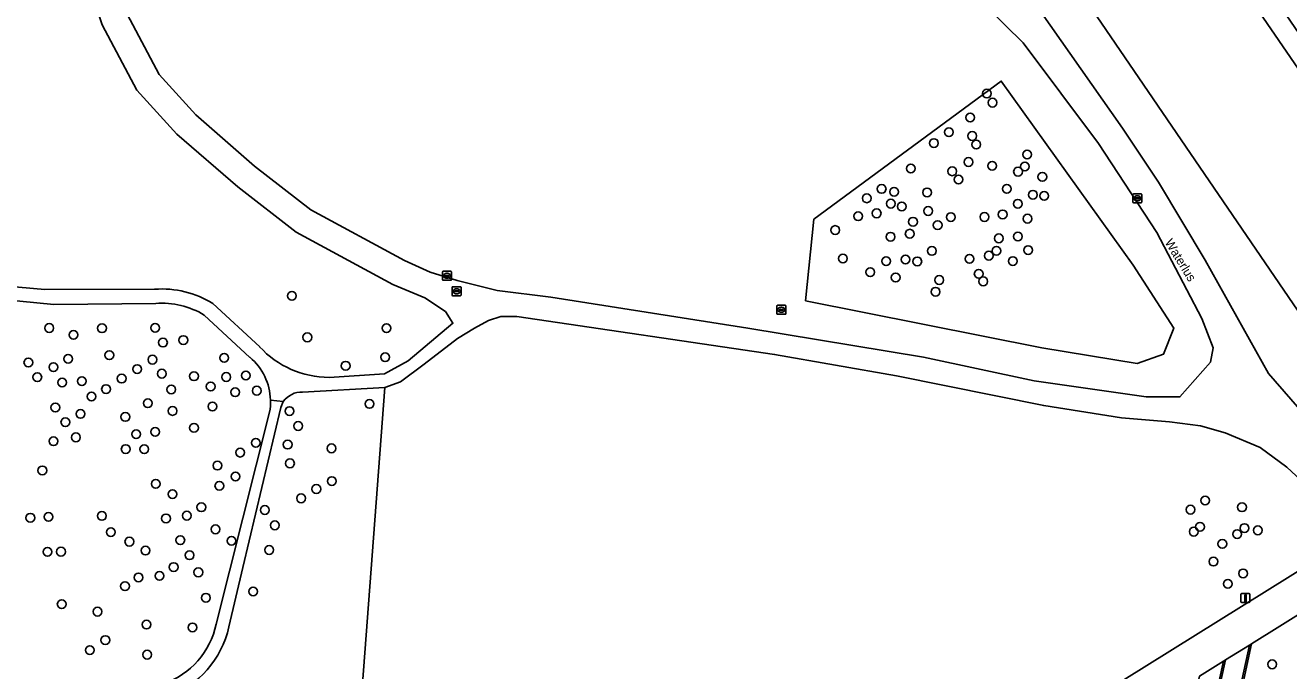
# Model space of a CAD drawing. Extents: x 155275 to 156265, y 382654 to 383635.
# Drawn here: x 155353.3 to 155494.7, y 383068.6 to 383140.8 of the extents above; entities that cross this region are included whole.
import ezdxf

# ---------------------------------------------------------------- set-up
doc = ezdxf.new("R2010")
doc.units = 0
for name, color, linetype in [('IMGEO_Boom', 7, 'Continuous'), ('IMGEO_Brandkraan', 7, 'Continuous'), ('IMGEO_Groenvoorziening', 7, 'Continuous'), ('IMGEO_Lichtmast', 7, 'Continuous'), ('IMGEO_Loofbos', 7, 'Continuous'), ('IMGEO_Openbare_ruimte_label', 7, 'Continuous'), ('IMGEO_Parkeervlak_halfverhard', 7, 'Continuous'), ('IMGEO_Parkeervlak_open', 7, 'Continuous'), ('IMGEO_Rijbaan_lokaal_halfverhard', 7, 'Continuous'), ('IMGEO_Rioolput', 7, 'Continuous'), ('IMGEO_Voetpad_halfverhard', 7, 'Continuous'), ('IMGEO_Voetpad_open', 7, 'Continuous')]:
    doc.layers.add(name, color=color, linetype=linetype)

msp = doc.modelspace()

# ---------------------------------------------------------------- linework, layer by layer
at = {"layer": 'IMGEO_Boom'}
for centre in [(155460.88, 383133.16), (155461.51, 383132.15), (155459.02, 383130.49), (155456.64, 383128.84), (155454.96, 383127.63), (155459.25, 383128.42), (155459.7, 383127.47), (155465.39, 383126.35), (155452.37, 383124.78), (155458.83, 383125.51), (155461.48, 383125.09), (155465.14, 383125.01), (155457.01, 383124.47), (155457.71, 383123.55), (155464.37, 383124.43), (155467.09, 383123.85), (155449.11, 383122.5), (155450.5, 383122.18), (155454.19, 383122.11), (155463.11, 383122.51), (155466.04, 383121.85), (155467.3, 383121.72), (155447.44, 383121.45), (155450.14, 383120.85), (155451.36, 383120.54), (155464.34, 383120.84), (155446.49, 383119.44), (155448.55, 383119.77), (155454.32, 383120.03), (155456.86, 383119.35), (155460.61, 383119.36), (155462.65, 383119.65), (155465.43, 383119.17), (155443.92, 383117.9), (155452.25, 383117.49), (155452.62, 383118.83), (155455.38, 383118.45), (155450.11, 383117.15), (155462.23, 383116.97), (155464.36, 383117.17), (155444.78, 383114.71), (155454.74, 383115.56), (155458.94, 383114.68), (155461.11, 383115.03), (155461.95, 383115.58), (155465.5, 383115.66), (155449.61, 383114.42), (155451.78, 383114.6), (155453.1, 383114.39), (155463.79, 383114.43), (155447.84, 383113.19), (155450.68, 383112.59), (155455.56, 383112.31), (155459.97, 383113), (155460.48, 383112.16), (155383.13, 383110.54), (155455.15, 383111), (155355.98, 383106.94), (155358.69, 383106.17), (155361.88, 383106.91), (155367.82, 383106.96), (155393.71, 383106.92), (155368.7, 383105.31), (155370.98, 383105.59), (155384.85, 383105.9), (155358.09, 383103.5), (155362.7, 383103.9), (155367.52, 383103.4), (155375.55, 383103.6), (155393.56, 383103.67), (155353.64, 383103.08), (155356.44, 383102.56), (155365.82, 383102.35), (155389.14, 383102.72), (155354.64, 383101.44), (155357.42, 383100.84), (155359.63, 383100.99), (155364.08, 383101.28), (155368.57, 383101.83), (155372.17, 383101.54), (155375.78, 383101.46), (155377.98, 383101.63), (155360.7, 383099.28), (155362.33, 383100.11), (155369.63, 383100.07), (155374.04, 383100.4), (155376.78, 383099.75), (155379.19, 383099.93), (155356.66, 383098.05), (155367, 383098.52), (155374.23, 383098.16), (155391.81, 383098.45), (155357.78, 383096.4), (155359.48, 383097.33), (155364.49, 383096.99), (155369.78, 383097.66), (155382.85, 383097.65), (155365.7, 383095.06), (155367.83, 383095.32), (155372.17, 383095.78), (155383.83, 383095.98), (155356.46, 383094.27), (155358.96, 383094.71), (155379.09, 383094.1), (155382.65, 383093.9), (155387.56, 383093.48), (155364.53, 383093.4), (155366.61, 383093.38), (155377.34, 383093), (155355.2, 383091.01), (155374.79, 383091.55), (155382.91, 383091.8), (155367.89, 383089.51), (155375.01, 383089.29), (155376.82, 383090.33), (155387.59, 383089.82), (155369.77, 383088.36), (155384.15, 383087.89), (155385.86, 383088.93), (155372.99, 383086.89), (155380.1, 383086.58), (155483.66, 383086.62), (155485.3, 383087.64), (155489.43, 383086.89), (155353.86, 383085.72), (155355.9, 383085.81), (155361.87, 383085.92), (155369.04, 383085.64), (155371.37, 383085.95), (155362.87, 383084.11), (155374.57, 383084.42), (155381.22, 383084.87), (155484.03, 383084.16), (155484.73, 383084.7), (155488.89, 383083.89), (155489.7, 383084.56), (155491.2, 383084.31), (155364.94, 383083.04), (155370.64, 383083.21), (155376.37, 383083.14), (155487.23, 383082.79), (155355.78, 383081.9), (155357.29, 383081.92), (155366.74, 383082.04), (155371.68, 383081.52), (155380.58, 383082.11), (155486.23, 383080.81), (155369.9, 383080.2), (155372.66, 383079.61), (155489.55, 383079.49), (155364.45, 383078.06), (155365.96, 383079.04), (155368.31, 383079.21), (155487.85, 383078.33), (155373.51, 383076.77), (155378.79, 383077.47), (155357.37, 383076.05), (155361.38, 383075.21), (155366.85, 383073.76), (155372, 383073.45), (155360.51, 383070.91), (155362.25, 383072.03), (155366.94, 383070.4), (155492.81, 383069.32)]:
    msp.add_circle(centre, 0.489, dxfattribs=at)
at = {"layer": 'IMGEO_Brandkraan'}
for p, q in [((155437.47, 383109.48), (155438.32, 383109.48)), ((155437.4, 383108.55), (155437.4, 383109.41)), ((155438.32, 383108.48), (155437.47, 383108.48)), ((155437.65, 383108.97), (155437.65, 383108.99)), ((155438.09, 383108.94), (155437.69, 383108.94)), ((155437.7, 383109.02), (155438.09, 383109.02)), ((155437.88, 383109.26), (155437.91, 383109.26)), ((155437.91, 383108.7), (155437.88, 383108.7)), ((155438.14, 383108.99), (155438.14, 383108.97)), ((155438.4, 383109.41), (155438.4, 383108.55))]:
    msp.add_line(p, q, dxfattribs=at)
for points in [[(155437.47, 383109.48), (155438.32, 383109.48)], [(155437.4, 383108.55), (155437.4, 383109.41)], [(155438.32, 383108.48), (155437.47, 383108.48)], [(155438.4, 383109.41), (155438.4, 383108.55)]]:
    msp.add_lwpolyline(points, dxfattribs=at)
for centre, radius, start, end in [((155437.47, 383109.4), 0.0765, 91.552, 178.448), ((155437.47, 383109.4), 0.0765, 91.552, 178.448), ((155438.32, 383109.4), 0.0765, 1.552, 88.448), ((155438.32, 383109.4), 0.0765, 1.552, 88.448), ((155437.47, 383108.55), 0.0765, 181.552, 268.448), ((155437.47, 383108.55), 0.0765, 181.552, 268.448), ((155437.69, 383108.98), 0.0403, 85.8775, 175.7526), ((155437.69, 383108.97), 0.0366, 178.938, 274.7102), ((155438.1, 383108.98), 0.0386, 1.7309, 96.639), ((155438.1, 383108.98), 0.043, 264.8664, 352.4533), ((155438.32, 383108.55), 0.0765, 271.552, 358.448), ((155438.32, 383108.55), 0.0765, 271.552, 358.448)]:
    msp.add_arc(centre, radius, start, end, dxfattribs=at)
for centre, major_axis, ratio, start_param, end_param in [((155437.88, 383108.98), (-0.387, 0.002), 0.722429, 4.712389, 7.853982), ((155437.91, 383108.98), (-0.39, 0.002), 0.717154, 1.570796, 4.712389)]:
    msp.add_ellipse(centre, major_axis=major_axis, ratio=ratio, start_param=start_param, end_param=end_param, dxfattribs=at)
at = {"layer": 'IMGEO_Groenvoorziening'}
for points in [[(155480.03, 383158.88), (155477.83, 383162.13), (155472.81, 383162.13), (155468.62, 383161.33), (155465.99, 383160.57), (155463.85, 383159.26), (155462.23, 383157.91), (155532.26, 383055.3), (155545.15, 383064.13), (155544.46, 383065.14), (155543.8, 383064.76), (155530.65, 383083.86), (155531.33, 383084.3), (155531.27, 383084.39), (155521.54, 383098.33)], [(155440.6, 383109.98), (155441.54, 383119.11), (155462.49, 383134.56), (155477.24, 383113.96), (155481.8, 383106.94), (155480.63, 383104.01), (155477.71, 383102.96), (155467.05, 383104.72)], [(155440.6, 383109.98), (155467.05, 383104.72), (155477.71, 383102.96), (155480.63, 383104.01), (155481.8, 383106.94), (155477.24, 383113.96), (155462.49, 383134.56), (155441.54, 383119.11)], [(155505.09, 383070.96), (155505.34, 383071.12), (155500.61, 383077.91), (155490.49, 383071.62), (155489.51, 383067.1), (155491.73, 383066.59), (155491.92, 383066.54), (155491.78, 383065.9), (155490.94, 383062.14)]]:
    msp.add_lwpolyline(points, close=True, dxfattribs=at)
for points in [[(155462.23, 383157.91), (155462.08, 383157.79), (155460.8, 383156.2), (155460.21, 383154.22), (155460.31, 383152.94), (155463.29, 383147.49), (155476.06, 383129.31), (155480.08, 383123.25), (155485.32, 383114.54), (155492.39, 383101.86), (155501.64, 383091.21), (155505.49, 383085.67), (155519.41, 383065.24), (155519.67, 383065.42), (155525.58, 383056.8)], [(155531.84, 383055.02), (155532.26, 383055.3), (155462.23, 383157.91)], [(155364.68, 383142.04), (155368.26, 383135.3), (155372.37, 383130.77), (155378.96, 383125.06), (155385.25, 383120.17), (155395.71, 383114.5), (155398.58, 383113.17), (155401.61, 383112.24), (155406.1, 383111.12), (155412.11, 383110.39), (155434.14, 383106.94), (155453.79, 383103.69), (155466.18, 383101.04), (155478.72, 383099.24), (155482.49, 383099.24), (155485.9, 383103.12), (155486.19, 383104.72), (155484.94, 383108), (155479.9, 383117.61), (155473.39, 383127.59), (155464.94, 383138.83), (155460.95, 383142.74)], [(155367.89, 383109.68), (155356.48, 383109.58), (155349.21, 383110.28)], [(155378.43, 383103.66), (155373.32, 383108.39)], [(155497.62, 383088.41), (155494.46, 383091.39), (155491.46, 383093.56), (155487.54, 383095.2), (155484.79, 383096.01), (155481.31, 383096.43), (155475.93, 383096.91), (155467.24, 383098.26), (155450.78, 383101.59), (155437.13, 383103.98), (155408.3, 383108.22), (155406.5, 383108.22), (155405.12, 383107.78), (155403.54, 383106.92), (155401.66, 383105.75), (155397.94, 383102.88), (155395.26, 383100.93), (155393.54, 383100.28), (155388.34, 383031.51), (155404.62, 383006.03), (155408.35, 383007.04), (155400.27, 383020.26), (155497.7, 383080.98)], [(155389.73, 383006.22), (155391.23, 383005.97), (155393.49, 383005.33), (155395.95, 383004.69), (155380.85, 383027.06), (155378.28, 383034.08), (155367.51, 383058.66), (155376.17, 383061.23), (155388.34, 383031.51), (155393.54, 383100.28)], [(155393.54, 383100.28), (155384.32, 383099.78)], [(155382.16, 383098.72), (155381.89, 383098.04), (155377.62, 383080.16), (155376.08, 383073.5)], [(155374.65, 383073.82), (155380.62, 383097.52)]]:
    msp.add_lwpolyline(points, dxfattribs=at)
for centre, radius, start, end in [((155368.57, 383100.49), 9.22, 58.989, 94.2431), ((155374.22, 383098.7), 6.51, 1.5857, 49.7196), ((155384.24, 383097.21), 2.57, 88.3524, 143.9444), ((155374.28, 383098.7), 6.46, 349.4798, 1.6068), ((155365.77, 383075.71), 9.09, 289.5801, 347.9592), ((155365.14, 383076.06), 11.24, 291.623, 346.8066)]:
    msp.add_arc(centre, radius, start, end, dxfattribs=at)
at = {"layer": 'IMGEO_Lichtmast'}
for p, q in [((155489.31, 383076.33), (155489.31, 383077.13)), ((155489.31, 383077.13), (155489.31, 383076.33)), ((155489.41, 383077.23), (155490.2, 383077.23)), ((155490.2, 383077.23), (155489.41, 383077.23)), ((155490.3, 383077.13), (155490.3, 383076.33)), ((155490.3, 383076.33), (155490.3, 383077.13)), ((155490.2, 383076.23), (155489.41, 383076.23)), ((155489.41, 383076.23), (155490.2, 383076.23))]:
    msp.add_line(p, q, dxfattribs=at)
msp.add_lwpolyline([(155489.73, 383077.1), (155489.88, 383077.1), (155489.88, 383076.35), (155489.73, 383076.35), (155489.73, 383077.1)], dxfattribs=at)
for centre, start, end in [((155489.41, 383077.13), 90, 180), ((155489.41, 383077.13), 90, 180), ((155490.2, 383077.13), 0, 90), ((155490.2, 383077.13), 360, 90), ((155489.41, 383076.33), 180, 270), ((155489.41, 383076.33), 180, 270), ((155490.2, 383076.33), 270, 0), ((155490.2, 383076.33), 270, 0)]:
    msp.add_arc(centre, 0.1, start, end, dxfattribs=at)
at = {"layer": 'IMGEO_Loofbos'}
for points in [[(155387.29, 383101.41), (155393.5, 383101.8), (155396.13, 383103.27), (155401.15, 383107.48), (155400.32, 383108.77), (155398, 383110.31), (155394.43, 383111.79), (155383.6, 383117.66), (155377.06, 383122.74), (155370.27, 383128.62), (155365.78, 383133.56), (155361.91, 383140.85), (155359.8, 383147.24), (155359.02, 383150.58), (155359.02, 383168.78), (155360.3, 383173.98), (155361.71, 383177.9), (155364.9, 383184), (155367.14, 383187.73), (155369.98, 383191.02), (155371.19, 383193.05), (155372.79, 383196.95), (155353.44, 383187.35)], [(155349.16, 383111.81), (155355.5, 383111.25), (155367.77, 383111.28)], [(155374.29, 383109.67), (155379.52, 383104.84)]]:
    msp.add_lwpolyline(points, dxfattribs=at)
for centre, radius, start, end in [((155368.57, 383100.5), 10.81, 58.0691, 94.2517), ((155387.29, 383111.96), 10.54, 222.4807, 269.9956)]:
    msp.add_arc(centre, radius, start, end, dxfattribs=at)
at = {"layer": 'IMGEO_Parkeervlak_halfverhard'}
for points in [[(155490.26, 383071.47), (155487.59, 383069.81), (155485.1, 383058.5), (155487.79, 383060.18)], [(155487.35, 383069.66), (155484.69, 383068), (155483.85, 383064.21), (155486.05, 383063.73)]]:
    msp.add_lwpolyline(points, close=True, dxfattribs=at)
at = {"layer": 'IMGEO_Parkeervlak_open'}
for points in [[(155489.51, 383067.1), (155490.49, 383071.62), (155490.38, 383071.54), (155490.26, 383071.47), (155487.79, 383060.18), (155487.91, 383060.26), (155488.03, 383060.33), (155489.36, 383066.44)], [(155487.59, 383069.81), (155487.47, 383069.74), (155487.35, 383069.66), (155486.05, 383063.73), (155485.72, 383062.26), (155484.86, 383058.35), (155484.98, 383058.43), (155485.1, 383058.5)]]:
    msp.add_lwpolyline(points, close=True, dxfattribs=at)
at = {"layer": 'IMGEO_Rijbaan_lokaal_halfverhard'}
for points in [[(155497.7, 383080.98), (155400.27, 383020.26), (155408.35, 383007.04), (155408.38, 383006.99), (155425.36, 383017.56)], [(155484.69, 383068), (155487.35, 383069.66), (155487.47, 383069.74), (155487.59, 383069.81), (155490.26, 383071.47), (155490.38, 383071.54), (155490.49, 383071.62), (155500.61, 383077.91)]]:
    msp.add_lwpolyline(points, dxfattribs=at)
at = {"layer": 'IMGEO_Rioolput'}
for p, q in [((155477.21, 383121.02), (155477.21, 383121.87)), ((155477.29, 383121.94), (155478.14, 383121.94)), ((155478.14, 383120.94), (155477.29, 383120.94)), ((155477.47, 383121.44), (155477.47, 383121.45)), ((155477.51, 383121.49), (155477.91, 383121.49)), ((155477.91, 383121.4), (155477.51, 383121.4)), ((155477.7, 383121.72), (155477.72, 383121.72)), ((155477.72, 383121.16), (155477.7, 383121.16)), ((155477.95, 383121.45), (155477.95, 383121.44)), ((155478.21, 383121.87), (155478.21, 383121.02)), ((155399.97, 383112.36), (155399.97, 383113.21)), ((155400.05, 383113.29), (155400.9, 383113.29)), ((155400.23, 383112.78), (155400.23, 383112.79)), ((155400.67, 383112.74), (155400.27, 383112.74)), ((155400.28, 383112.83), (155400.67, 383112.83)), ((155400.46, 383113.06), (155400.49, 383113.06)), ((155400.48, 383112.51), (155400.46, 383112.51)), ((155400.72, 383112.79), (155400.72, 383112.78)), ((155400.98, 383113.21), (155400.98, 383112.36)), ((155400.9, 383112.28), (155400.05, 383112.28)), ((155401.05, 383110.63), (155401.05, 383111.48)), ((155401.12, 383111.55), (155401.98, 383111.55)), ((155401.31, 383111.05), (155401.31, 383111.06)), ((155401.35, 383111.1), (155401.75, 383111.1)), ((155401.74, 383111.01), (155401.35, 383111.01)), ((155401.54, 383111.33), (155401.56, 383111.33)), ((155401.79, 383111.06), (155401.79, 383111.05)), ((155402.05, 383111.48), (155402.05, 383110.63)), ((155401.98, 383110.55), (155401.12, 383110.55)), ((155401.56, 383110.77), (155401.53, 383110.77))]:
    msp.add_line(p, q, dxfattribs=at)
for points in [[(155477.21, 383121.02), (155477.21, 383121.87)], [(155477.29, 383121.94), (155478.14, 383121.94)], [(155478.14, 383120.94), (155477.29, 383120.94)], [(155478.21, 383121.87), (155478.21, 383121.02)], [(155399.97, 383112.36), (155399.97, 383113.21)], [(155400.05, 383113.29), (155400.9, 383113.29)], [(155400.98, 383113.21), (155400.98, 383112.36)], [(155400.9, 383112.28), (155400.05, 383112.28)], [(155401.05, 383110.63), (155401.05, 383111.48)], [(155401.12, 383111.55), (155401.98, 383111.55)], [(155402.05, 383111.48), (155402.05, 383110.63)], [(155401.98, 383110.55), (155401.12, 383110.55)]]:
    msp.add_lwpolyline(points, dxfattribs=at)
for centre, radius, start, end in [((155477.29, 383121.87), 0.0765, 91.552, 178.448), ((155477.29, 383121.87), 0.0765, 91.552, 178.448), ((155477.29, 383121.02), 0.0765, 181.552, 268.448), ((155477.29, 383121.02), 0.0765, 181.552, 268.448), ((155477.51, 383121.45), 0.0403, 85.8775, 175.7526), ((155477.51, 383121.44), 0.0366, 178.938, 274.7102), ((155477.92, 383121.45), 0.0386, 1.7309, 96.639), ((155477.91, 383121.44), 0.043, 264.8664, 352.4533), ((155478.14, 383121.87), 0.0765, 1.552, 88.448), ((155478.14, 383121.87), 0.0765, 1.552, 88.448), ((155478.14, 383121.02), 0.0765, 271.552, 358.448), ((155478.14, 383121.02), 0.0765, 271.552, 358.448), ((155400.05, 383113.21), 0.0765, 91.552, 178.448), ((155400.05, 383113.21), 0.0765, 91.552, 178.448), ((155400.05, 383112.36), 0.0765, 181.552, 268.448), ((155400.05, 383112.36), 0.0765, 181.552, 268.448), ((155400.27, 383112.79), 0.0403, 85.8775, 175.7526), ((155400.27, 383112.78), 0.0366, 178.938, 274.7102), ((155400.68, 383112.79), 0.0386, 1.7309, 96.639), ((155400.67, 383112.78), 0.043, 264.8664, 352.4533), ((155400.9, 383113.21), 0.0765, 1.552, 88.448), ((155400.9, 383113.21), 0.0765, 1.552, 88.448), ((155400.9, 383112.36), 0.0765, 271.552, 358.448), ((155400.9, 383112.36), 0.0765, 271.552, 358.448), ((155401.12, 383111.48), 0.0765, 91.552, 178.448), ((155401.12, 383111.48), 0.0765, 91.552, 178.448), ((155401.35, 383111.06), 0.0403, 85.8775, 175.7526), ((155401.34, 383111.05), 0.0366, 178.938, 274.7102), ((155401.75, 383111.05), 0.043, 264.8664, 352.4533), ((155401.75, 383111.06), 0.0386, 1.7309, 96.639), ((155401.97, 383111.48), 0.0765, 1.552, 88.448), ((155401.97, 383111.48), 0.0765, 1.552, 88.448), ((155401.12, 383110.63), 0.0765, 181.552, 268.448), ((155401.12, 383110.63), 0.0765, 181.552, 268.448), ((155401.97, 383110.63), 0.0765, 271.552, 358.448), ((155401.97, 383110.63), 0.0765, 271.552, 358.448)]:
    msp.add_arc(centre, radius, start, end, dxfattribs=at)
for centre, major_axis, ratio, start_param, end_param in [((155477.7, 383121.44), (-0.387, 0.002), 0.722429, 4.712389, 7.853982), ((155477.72, 383121.44), (-0.39, 0.002), 0.717154, 1.570796, 4.712389), ((155400.46, 383112.78), (-0.387, 0.002), 0.722429, 4.712389, 7.853982), ((155400.49, 383112.78), (-0.39, 0.002), 0.717154, 1.570796, 4.712389), ((155401.54, 383111.05), (-0.387, 0.002), 0.722429, 4.712389, 7.853982), ((155401.56, 383111.05), (-0.39, 0.002), 0.717154, 1.570796, 4.712389)]:
    msp.add_ellipse(centre, major_axis=major_axis, ratio=ratio, start_param=start_param, end_param=end_param, dxfattribs=at)
at = {"layer": 'IMGEO_Voetpad_halfverhard'}
for points in [[(155501.64, 383091.21), (155492.39, 383101.86), (155485.32, 383114.54), (155480.08, 383123.25), (155476.06, 383129.31), (155463.29, 383147.49)], [(155460.95, 383142.74), (155464.94, 383138.83), (155473.39, 383127.59), (155479.9, 383117.61), (155484.94, 383108), (155486.19, 383104.72), (155485.9, 383103.12), (155482.49, 383099.24), (155478.72, 383099.24), (155466.18, 383101.04), (155453.79, 383103.69), (155434.14, 383106.94), (155412.11, 383110.39), (155406.1, 383111.12), (155401.61, 383112.24), (155398.58, 383113.17), (155395.71, 383114.5), (155385.25, 383120.17), (155378.96, 383125.06), (155372.37, 383130.77), (155368.26, 383135.3), (155364.68, 383142.04)], [(155361.91, 383140.85), (155365.78, 383133.56), (155370.27, 383128.62), (155377.06, 383122.74), (155383.6, 383117.66), (155394.43, 383111.79), (155398, 383110.31), (155400.32, 383108.77), (155401.15, 383107.48), (155396.13, 383103.27), (155393.5, 383101.8), (155387.29, 383101.41)], [(155367.77, 383111.28), (155355.5, 383111.25), (155349.16, 383111.81)], [(155349.21, 383110.28), (155356.48, 383109.58), (155367.89, 383109.68)], [(155379.52, 383104.84), (155374.29, 383109.67)], [(155373.32, 383108.39), (155378.43, 383103.66)], [(155384.32, 383099.78), (155393.54, 383100.28), (155395.26, 383100.93), (155397.94, 383102.88), (155401.66, 383105.75), (155403.54, 383106.92), (155405.12, 383107.78), (155406.5, 383108.22), (155408.3, 383108.22), (155437.13, 383103.98), (155450.78, 383101.59), (155467.24, 383098.26), (155475.93, 383096.91), (155481.31, 383096.43), (155484.79, 383096.01), (155487.54, 383095.2), (155491.46, 383093.56), (155494.46, 383091.39), (155497.62, 383088.41)], [(155376.08, 383073.5), (155377.62, 383080.16), (155381.89, 383098.04), (155382.16, 383098.72), (155380.73, 383098.88)], [(155380.73, 383098.88), (155382.16, 383098.72)], [(155380.62, 383097.52), (155374.65, 383073.82)]]:
    msp.add_lwpolyline(points, dxfattribs=at)
for centre, radius, start, end in [((155368.57, 383100.5), 10.81, 58.0691, 94.2517), ((155368.57, 383100.49), 9.22, 58.989, 94.2431), ((155387.29, 383111.96), 10.54, 222.4807, 269.9956), ((155374.22, 383098.7), 6.51, 1.5857, 49.7196), ((155384.24, 383097.21), 2.57, 88.3524, 143.9444), ((155374.28, 383098.7), 6.46, 349.4798, 1.6068), ((155365.77, 383075.71), 9.09, 289.5801, 347.9592), ((155365.14, 383076.06), 11.24, 291.623, 346.8066)]:
    msp.add_arc(centre, radius, start, end, dxfattribs=at)
at = {"layer": 'IMGEO_Voetpad_open'}
msp.add_lwpolyline([(155481.73, 383160.46), (155480.36, 383162.48), (155478.43, 383165.32), (155476.98, 383167.45), (155474.79, 383166.6), (155477.83, 383162.13), (155480.03, 383158.88), (155521.54, 383098.33), (155531.27, 383084.39), (155531.33, 383084.3), (155543.38, 383066.69), (155544.46, 383065.14), (155546.39, 383066.3), (155534.05, 383084.39), (155536.9, 383086.72), (155550.09, 383095.76), (155549.47, 383096.7), (155548.45, 383098.26), (155535.7, 383087.84), (155533.1, 383085.72), (155519.95, 383104.72), (155502.38, 383130.28)], close=True, dxfattribs=at)

# ---------------------------------------------------------------- texts
at = {"layer": 'IMGEO_Openbare_ruimte_label'}
msp.add_text('Waterlus', height=1, rotation=301.4649, dxfattribs=at).set_placement((155480.75, 383116.53))

doc.saveas('drawing.dxf')
